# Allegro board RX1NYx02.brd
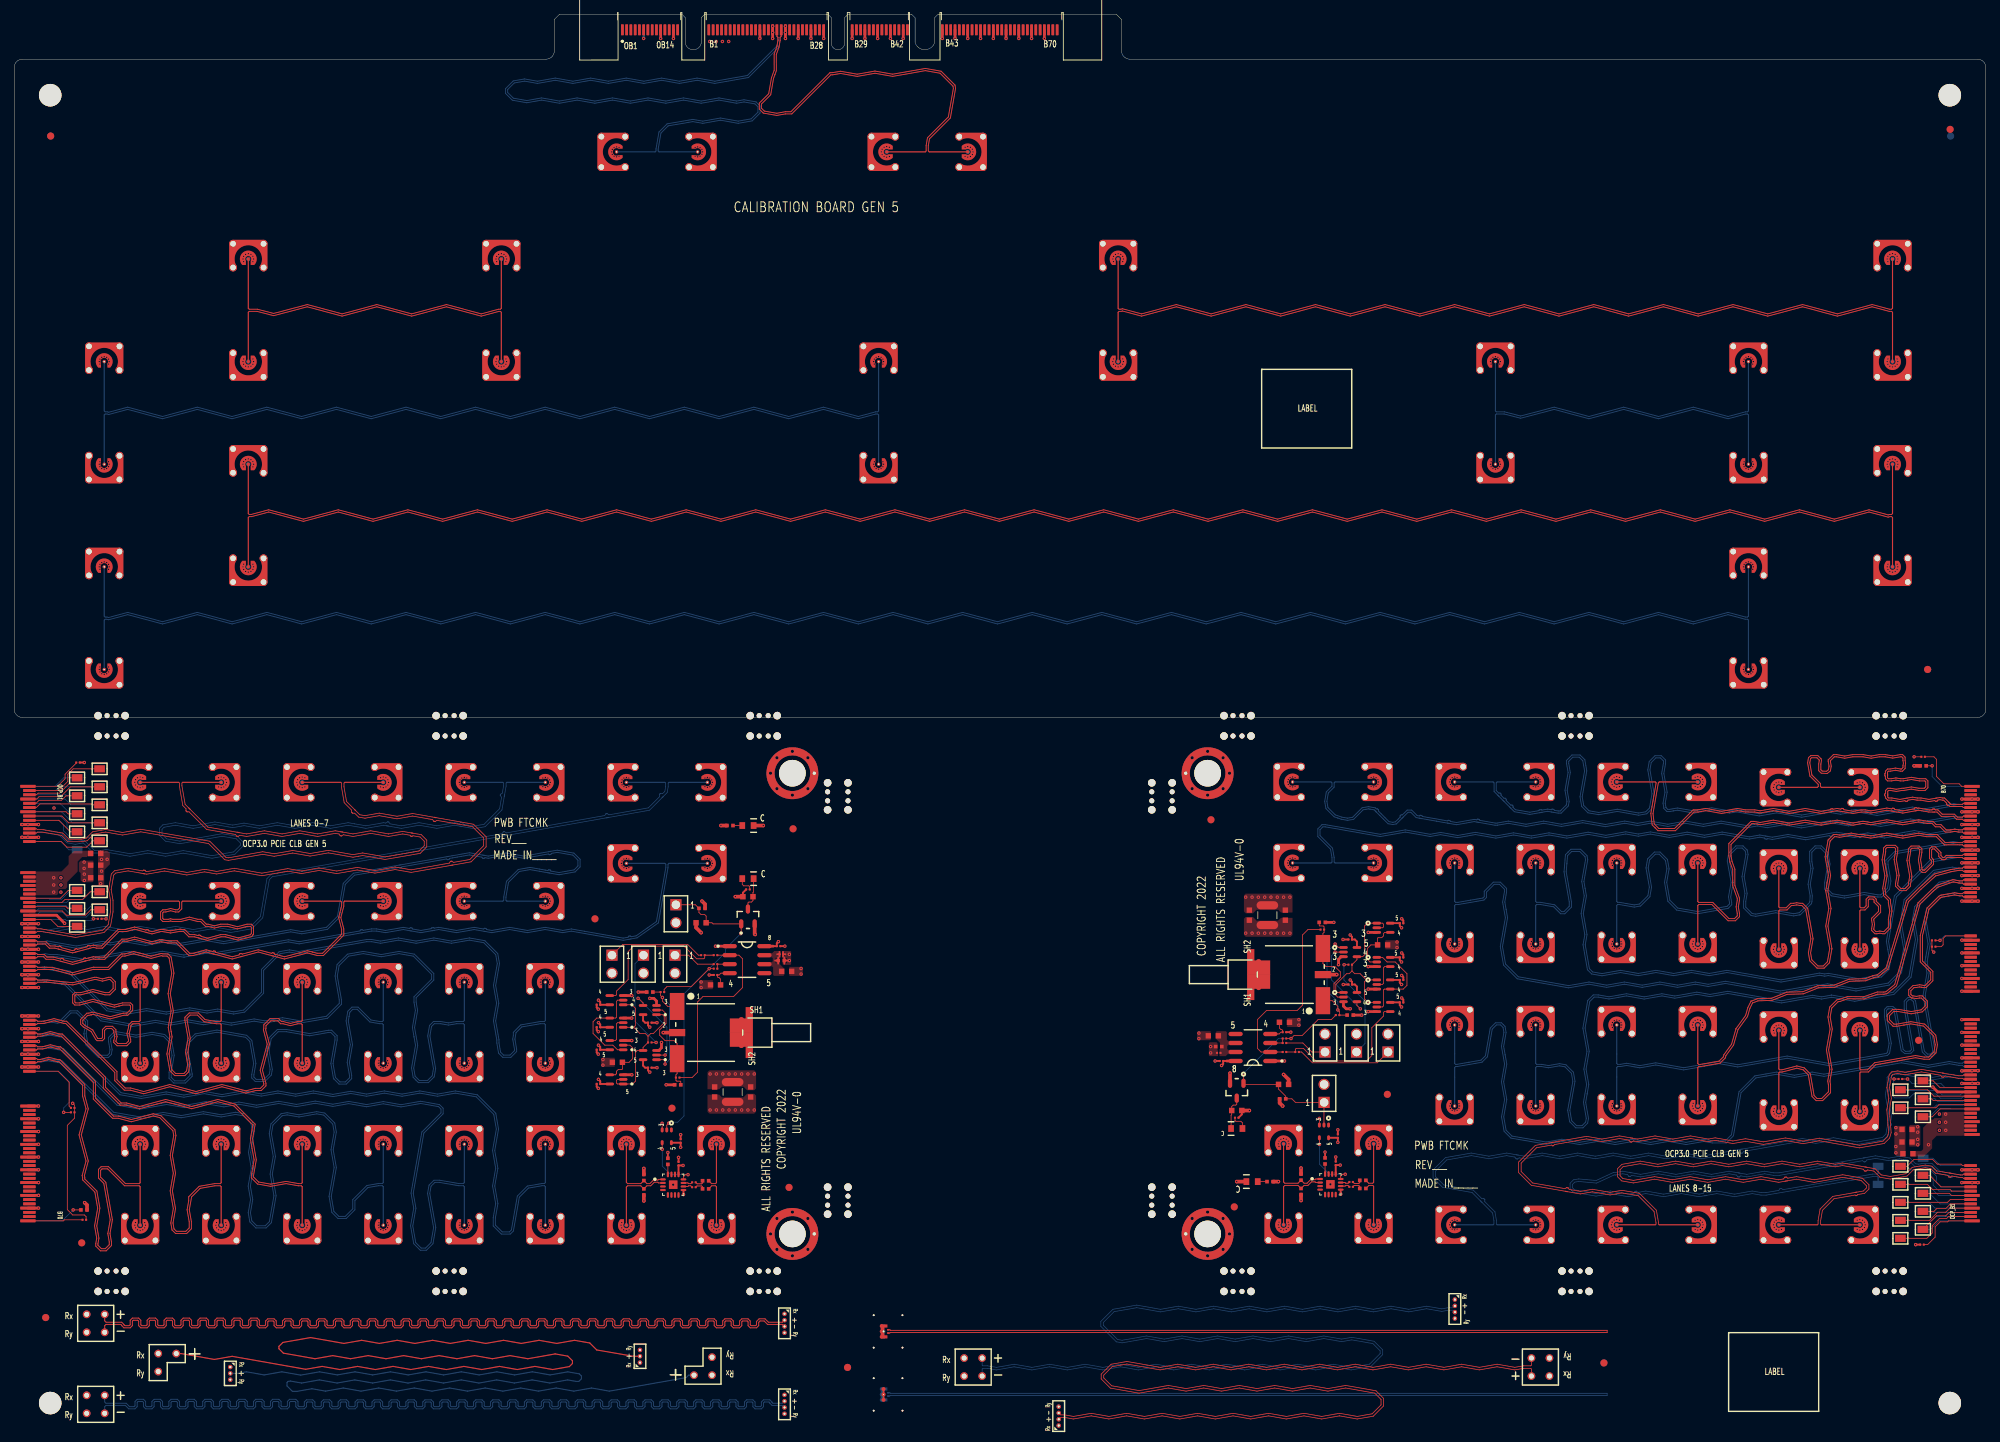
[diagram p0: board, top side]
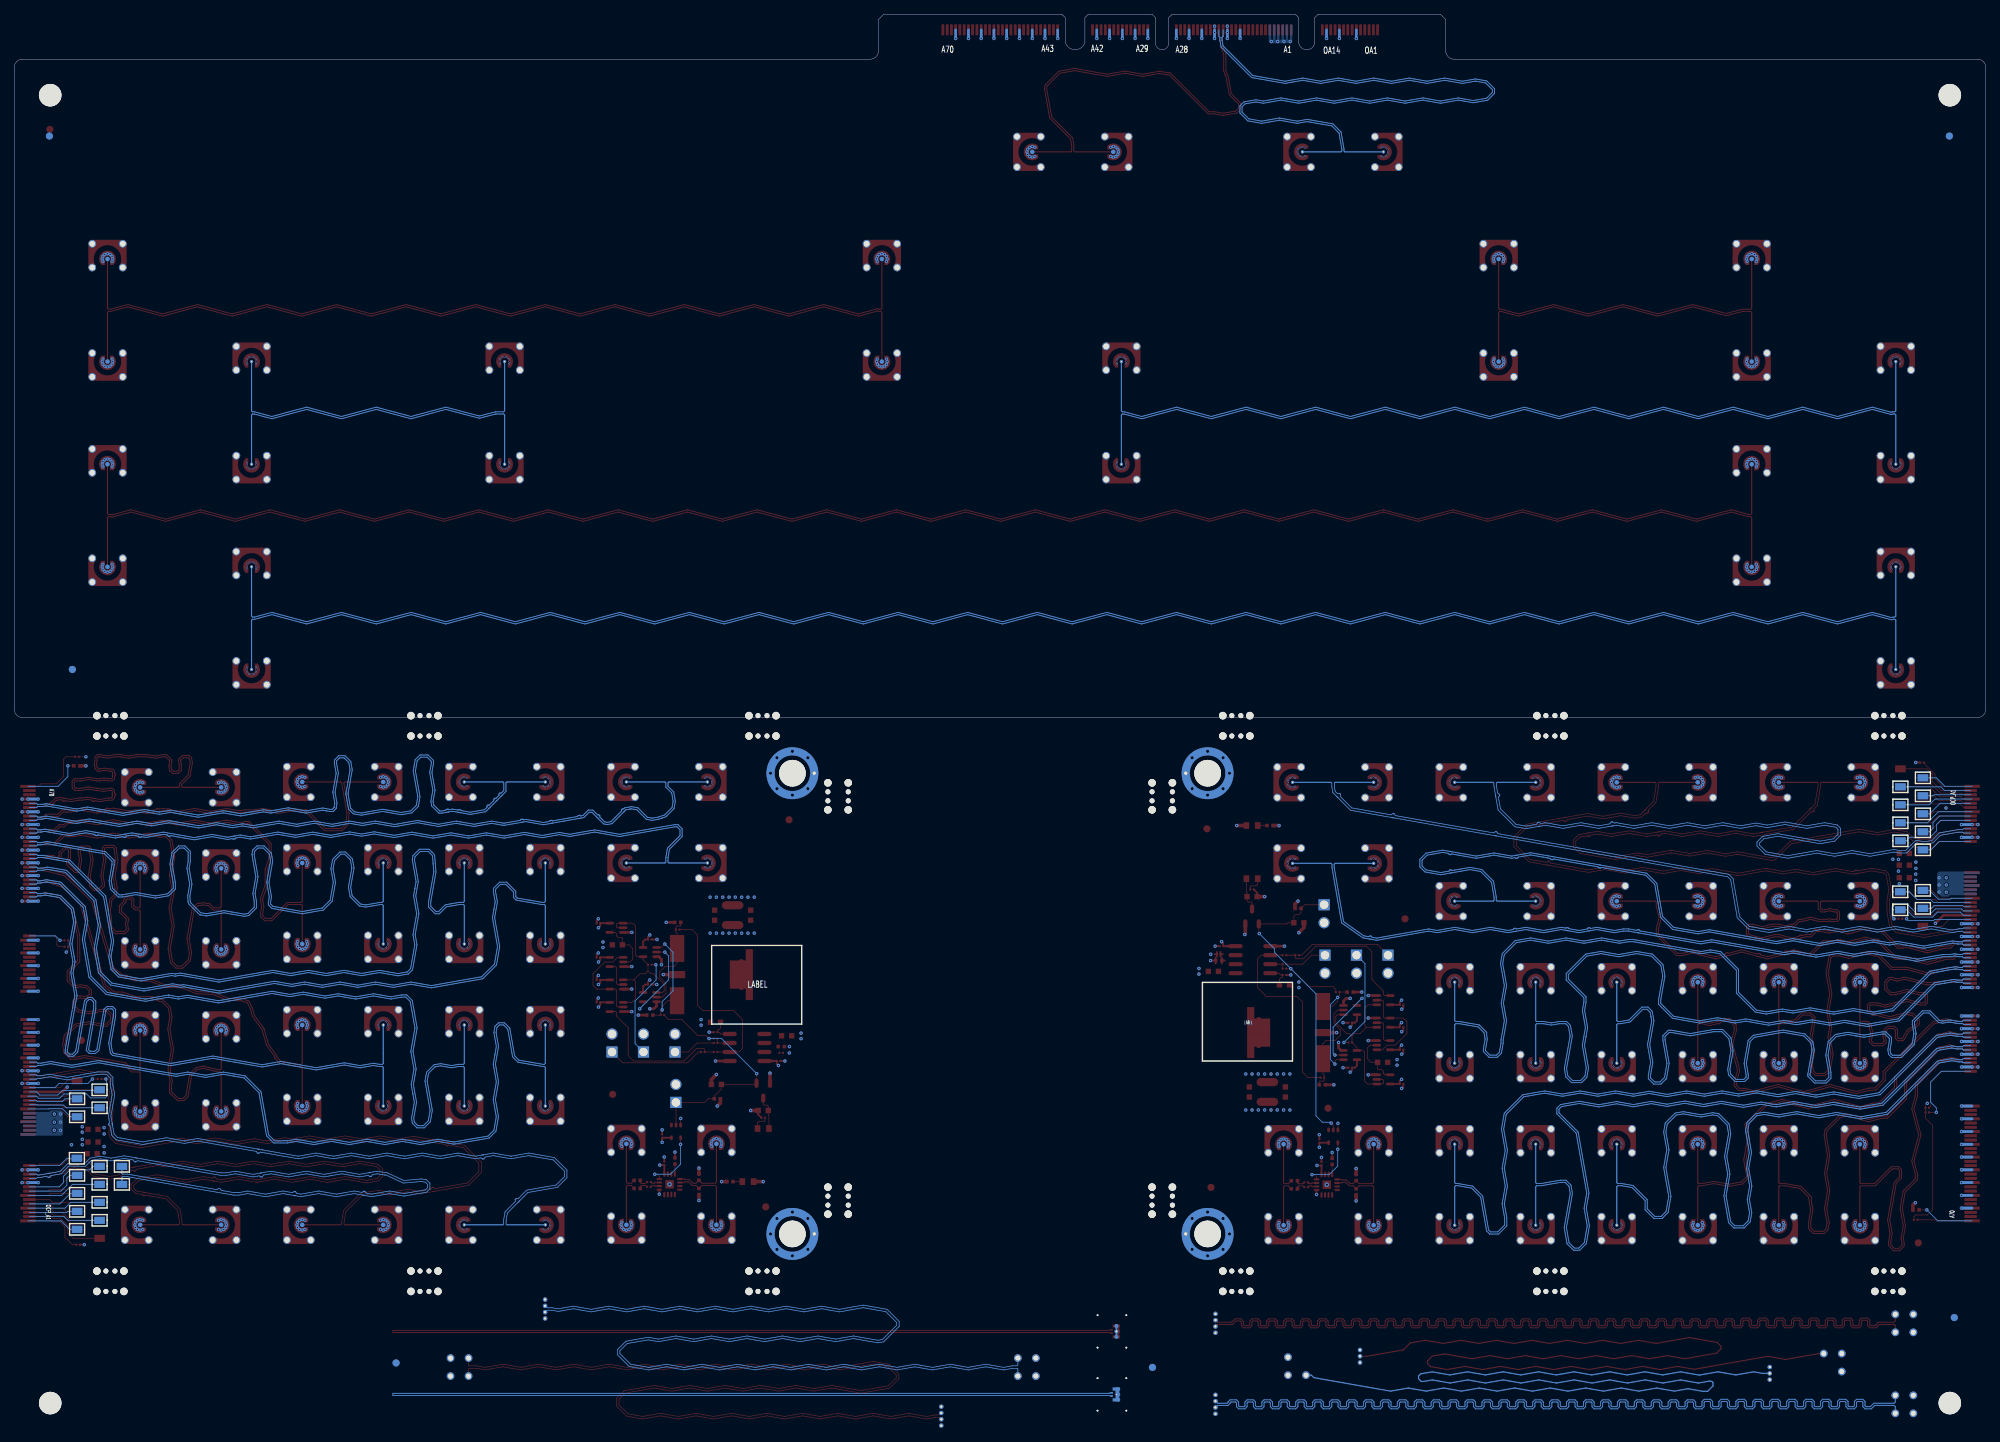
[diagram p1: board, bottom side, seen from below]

Outline 278.08 x 99.23 mm; copper layers: TOP, GND, VCC, GD2, GD3, BOTTOM. Coordinates in mm from the lower left corner of the outline.
Outline path: 0,91.7 arc(0.35,92.54) 1.18,92.88 75,92.88 arc(75.84,93.23) 76.18,94.06 76.18,98.48 76.93,99.23 94.04,99.23 94.16,99.23 94.66,98.73 94.66,95.3 arc(94.97,94.54) 95.72,94.23 95.84,94.23 arc(96.59,94.54) 96.91,95.3 96.91,98.73 97.41,99.23 97.53,99.23 114.51,99.23 114.76,99.23 115.26,98.73 115.26,95.12 arc(115.52,94.49) 116.15,94.23 116.22,94.23 arc(116.85,94.49) 117.11,95.12 117.11,98.48 117.11,98.73 117.61,99.23 117.86,99.23 126.45,99.23 126.57,99.23 127.07,98.73 127.07,95.23 arc(127.57,94.51) 128.41,94.23 128.47,94.23 arc(129.31,94.51) 129.82,95.23 129.82,98.73 130.32,99.23 130.44,99.23 155.43,99.23 156.18,98.48 156.18,94.06 arc(156.53,93.23) 157.36,92.88 276.9,92.88 arc(277.74,92.54) 278.08,91.7 278.08,1.18 arc(277.74,0.35) 276.9,0 1.18,0 arc(0.35,0.35) 0,1.18 0,91.7

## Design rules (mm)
constraint set DEFAULT: min track width 0.102
net group BD1_555_OUT: nets BD1_555_OUT BD1_555_OUT_JP
net group CLK1_TRIG_SIGNAL_C_DN: nets CLK1_TRIG_SIGNAL_C_DN CLK1_TRIG_SIGNAL_R_DN
net group CLK1_TRIG_SIGNAL_C_DP: nets CLK1_TRIG_SIGNAL_C_DP CLK1_TRIG_SIGNAL_R_DP
net group CLK2_TRIG_SIGNAL_C_DN: nets CLK2_TRIG_SIGNAL_C_DN CLK2_TRIG_SIGNAL_R_DN
net group CLK2_TRIG_SIGNAL_C_DP: nets CLK2_TRIG_SIGNAL_C_DP CLK2_TRIG_SIGNAL_R_DP
net group N16712697: nets N16712697 N16712704
net group N16815513: nets N16815513 N16816677
net group SET2DIL: nets SET2DIL_85_BOT SET2DIL_85_TOP
net group V_12V_1: nets N16866749 N16866751
net group V_12V_2: nets N16879387 N16879389
net group 12V: nets V_12V_2
net group _UNCONSTRAINED: nets BD1_AUX_PWR_EN BD1_BIF0_N BD1_BIF1_N BD1_BIF2_N BD1_MAIN_PWR_EN BD1_NCSI_ARBIN BD1_NCSI_ARBOUT BD1_NCSI_CRS_DV BD1_NCSI_RXD0 BD1_NCSI_RXD1 BD1_NCSI_TXD0 BD1_NCSI_TXD1 BD1_NCSI_TXEN BD1_NIC_PWR_GOOD BD1_PWRBRK_N BD1_SCAN_DATA_IN BD1_SCAN_DATA_OUT BD1_SCAN_LD_N BD1_SLOT_ID BD1_SMB_SDA BD1_WAKE_N BD2_AUX_PWR_EN BD2_BIF0_N BD2_BIF1_N BD2_BIF2_N BD2_MAIN_PWR_EN BD2_NCSI_ARBIN BD2_NCSI_ARBOUT BD2_NCSI_CRS_DV BD2_NCSI_RXD0 BD2_NCSI_RXD1 BD2_NCSI_TXD0 BD2_NCSI_TXD1 BD2_NCSI_TXEN BD2_NIC_PWR_GOOD BD2_PWRBRK_N BD2_SCAN_DATA_IN BD2_SCAN_DATA_OUT BD2_SCAN_LD_N BD2_SLOT_ID BD2_SMB_SDA BD2_WAKE_N
net group BD1_555_TRI: nets BD1_555_TRI BD1_BTN_NO N16713764 N16713990
net group BD1_PRSNTA_N: nets BD1_PRSNTA_N BD1_PRSNTB0_N BD1_PRSNTB1_N BD1_PRSNTB2_N BD1_PRSNTB3_N
net group BD2_555_OUT: nets BD2_555_OUT BD2_555_OUT_JP BD2_BTN_NC
net group BD2_555_TRI: nets BD2_555_TRI N16815728 N16815771
net group BD2_PRSNTA_N: nets BD2_PRSNTA_N BD2_PRSNTB0_N BD2_PRSNTB1_N BD2_PRSNTB2_N BD2_PRSNTB3_N
net group BD_REFCLK: nets BD1_REFCLK0_DN BD1_REFCLK0_DP BD1_REFCLK1_DN BD1_REFCLK1_DP BD1_REFCLK2_DN BD1_REFCLK2_DP BD1_REFCLK3_DN BD1_REFCLK3_DP BD2_REFCLK0_DN BD2_REFCLK0_DP BD2_REFCLK1_DN BD2_REFCLK1_DP BD2_REFCLK2_DP BD2_REFCLK3_DN BD2_REFCLK3_DP
net group CLK_DIFF: nets CLK1_HOST_TO_TRIGGER_DN CLK1_HOST_TO_TRIGGER_DP CLK2_HOST_TO_TRIGGER_DN CLK2_HOST_TO_TRIGGER_DP
net group CLK_SE: nets BD1_CLK_NCSI BD1_SCAN_CLK BD1_SMB_CLK BD2_CLK_NCSI BD2_SCAN_CLK BD2_SMB_CLK
net group COUPONS: nets Z_42.5_BOT Z_42.5_TOP Z_85D_BOT_DN Z_85D_BOT_DP Z_85D_TOP_DN Z_85D_TOP_DP Z_100D_BOT_DN Z_100D_BOT_DP Z_100D_TOP_DN Z_100D_TOP_DP
net group PE_SIGNALS: nets BD2_PE_OCP_CPU_0_DN BD2_PE_OCP_CPU_0_DP PE_CAL_BOT_OCP_CPU_0_DN PE_CAL_BOT_OCP_CPU_0_DP PE_CPU_OCP_0_DN PE_CPU_OCP_0_DP PE_CPU_OCP_1_DN PE_CPU_OCP_1_DP PE_CPU_OCP_2_DN PE_CPU_OCP_2_DP PE_CPU_OCP_3_DN PE_CPU_OCP_3_DP PE_CPU_OCP_4_DN PE_CPU_OCP_4_DP PE_CPU_OCP_5_DN PE_CPU_OCP_5_DP PE_CPU_OCP_6_DN PE_CPU_OCP_6_DP PE_CPU_OCP_7_DN PE_CPU_OCP_7_DP PE_CPU_OCP_8_DN PE_CPU_OCP_8_DP PE_CPU_OCP_9_DN PE_CPU_OCP_9_DP PE_CPU_OCP_10_DN PE_CPU_OCP_10_DP PE_CPU_OCP_11_DN PE_CPU_OCP_11_DP PE_CPU_OCP_12_DN PE_CPU_OCP_12_DP PE_CPU_OCP_13_DN PE_CPU_OCP_13_DP PE_CPU_OCP_14_DN PE_CPU_OCP_14_DP PE_CPU_OCP_15_DN PE_CPU_OCP_15_DP PE_OCP_CPU_0_DN PE_OCP_CPU_0_DP PE_OCP_CPU_1_DN PE_OCP_CPU_1_DP PE_OCP_CPU_2_DN PE_OCP_CPU_2_DP PE_OCP_CPU_3_DN PE_OCP_CPU_3_DP PE_OCP_CPU_4_DN PE_OCP_CPU_5_DN PE_OCP_CPU_5_DP PE_OCP_CPU_6_DN PE_OCP_CPU_6_DP PE_OCP_CPU_7_DN PE_OCP_CPU_7_DP PE_OCP_CPU_8_DN PE_OCP_CPU_8_DP PE_OCP_CPU_9_DN PE_OCP_CPU_9_DP PE_OCP_CPU_10_DN PE_OCP_CPU_10_DP PE_OCP_CPU_11_DN PE_OCP_CPU_11_DP PE_OCP_CPU_12_DN PE_OCP_CPU_12_DP PE_OCP_CPU_13_DN PE_OCP_CPU_13_DP PE_OCP_CPU_14_DN PE_OCP_CPU_14_DP PE_OCP_CPU_15_DN PE_OCP_CPU_15_DP
net group RESETS: nets BD1_555_RST_N BD1_PERST0_N BD1_PERST1_N BD1_PERST2_N BD1_PERST3_N BD1_SMB_RST_N BD2_555_RST_N BD2_PERST0_N BD2_PERST1_N BD2_PERST2_N BD2_PERST3_N BD2_SLOT_ID1 BD2_SMB_RST_N
nets with their own width: min track width 0.508; nets V_12V_1

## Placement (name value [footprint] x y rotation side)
BD2_P_OCP_CPU_0_N  COAX,FEMALE  [96_MMPX-50-0-3_L1_CASEA]  203.17 -54.81 90 top
BD2_P_OCP_CPU_0_P  COAX,FEMALE  [96_MMPX-50-0-3_L1_CASEA]  203.17 -43.38 270 top
C1  0.1uF  [C0201]  107.81 -32.26 0 top
C2  0.1uF  [C0201]  89.65 -49.41 180 top
C3  0.1uF  [C0201]  82.41 -43.69 0 top
C4  0.1uF  [C0201]  82.41 -40.52 0 top
C5  0.1uF  [C0201]  82.41 -51.69 0 top
C6  10uF  [C0603]  108.95 -35.82 0 top
C7  10uF  [C0603]  98.92 -37.72 180 top
C8  0.1uF  [C0201]  89.65 -43.06 180 top
C9  0.1uF  [C0201]  82.41 -46.87 0 top
C10  10uF  [C0603]  85.07 -48.64 180 top
C11  0.1uF  [C0201]  95.87 -66.27 180 top
C12  0.1uF  [C0201]  95.87 -65.59 180 top
C13  100uF  [C1210_107H]  101.33 -52.84 90 top
C15  2.2uF  [C0603]  103.87 -52.84 90 top
C16  0.1uF  [C0201]  93.7 -62.95 90 top
C20  2.2uF  [C0603]  11.49 -22.61 180 top
C73  10uF  [C0603]  266.97 -59.89 180 top
C74  2.2uF  [C0603]  266.97 -58.12 0 top
C75  0.1uF  [C0201]  170.27 -48.46 180 top
C76  0.1uF  [C0201]  188.44 -31.32 0 top
C77  0.1uF  [C0201]  195.67 -37.03 180 top
C78  0.1uF  [C0201]  195.67 -40.21 180 top
C79  0.1uF  [C0201]  195.67 -29.03 180 top
C80  10uF  [C0603]  169.13 -44.91 180 top
C81  10uF  [C0603]  179.16 -43 0 top
C82  0.1uF  [C0201]  188.44 -37.67 0 top
C83  0.1uF  [C0201]  195.67 -33.86 180 top
C84  10uF  [C0603]  193.01 -32.08 0 top
C85  0.1uF  [C0201]  186.39 -62.9 90 top
C86  0.1uF  [C0201]  188.56 -66.22 180 top
C87  100uF  [C1210_107H]  176.75 -27.89 270 top
C88  10uF  [C0603]  179.29 -27.89 90 top
C89  2.2uF  [C0603]  174.21 -27.89 270 top
C90  0.1uF  [C0201]  188.56 -65.53 180 top
C145  2.2uF  [C0603]  11.49 -19.18 180 top
C146  10uF  [C0603]  11.49 -20.83 180 top
C147  10uF  [C0603]  98.79 -52.84 90 top
C148  0.056uF  [C0402]  88.81 -64.9 270 top
C149  0.056uF  [C0402]  88.81 -66.93 90 top
C150  10uF  [C0603]  103.49 -25.28 180 top
C155  2.2uF  [C0603]  267.1 -61.54 0 top
C156  0.056uF  [C0402]  181.5 -64.85 270 top
C157  10uF  [C0603]  172.43 -55.45 0 top
C158  0.056uF  [C0402]  181.5 -66.88 90 top
C163  1uF  [C0603]  96.89 -28.96 0 top
C165  1uF  [C0603]  179.04 -51.77 180 top
C166  0.1uF  [C0201]  94 -59.75 90 top
C167  0.1uF  [C0201]  186.69 -59.06 90 top
DS_BD1_PWR  APH1608-TD47  [LEDC1608X65N]  103.49 -15.24 0 top
DS_BD1_TRIG  APH1608-TD47  [LEDC1608X65N]  103.49 -22.74 0 top
DS_BD2_PWR  APH1608-TD47  [LEDC1608X65N]  174.59 -65.48 180 top
DS_BD2_TRIG  APH1608-TD47  [LEDC1608X65N]  172.43 -57.99 180 top
J_S2D_BOT  SET2DIL,COUPON  [TP3_PPROBEB]  122.62 -95.51 0 bottom
J_S2D_TOP  SET2DIL,COUPON  [TP3_PPROBEB]  122.62 -86.62 0 top
LBL1  2d_label500x437  [2D_LABEL500X437]  110.49 -48.47 180 bottom
LBL3  2d_label500x437  [2D_LABEL500X437]  179.71 -43.26 180 bottom
LBL4  2d_label500x437  [2D_LABEL500X437]  241.81 -97.89 0 top
LBL5  2d_label500x437  [2D_LABEL500X437]  175.95 38.02 0 top
MH1  .148 DRILL,.288 PAD TOP/BTM  [MH148_G8_288TB]  109.76 -72.86 0 top
MH2  .148 DRILL,.288 PAD TOP/BTM  [MH148_G8_288TB]  109.76 -7.86 0 top
MH5  .148 DRILL,.288 PAD TOP/BTM  [MH148_G8_288TB]  168.32 -72.86 180 top
MH6  .148 DRILL,.288 PAD TOP/BTM  [MH148_G8_288TB]  168.32 -7.86 180 top
NOREF  -  [unnamed]  168.8 -14.43 180 top
NOREF#2  -  [unnamed#2]  61.41 -80.97 0 top
NOREF#3  -  [unnamed#2]  114.73 -68.17 90 top
NOREF#4  -  [unnamed#2]  13.74 -80.97 0 top
NOREF#5  -  [unnamed#2]  264.51 -2.61 0 top
NOREF#6  -  [unnamed]  109.86 -15.7 0 top
NOREF#7  -  [unnamed#2]  163.32 -68.17 90 top
NOREF#8  -  [#3]  0 -101.17 0 top
NOREF#9  -  [unnamed#2]  117.6 -68.17 90 top
NOREF#10  -  [#3]  5.08 -96.73 0 top
NOREF#11  -  [unnamed#2]  114.73 -11.12 90 top
NOREF#12  -  [unnamed]  269.88 6.78 180 top
NOREF#13  -  [unnamed#2]  160.45 -11.12 90 top
NOREF#14  -  [unnamed#2]  172.54 -80.97 0 top
NOREF#15  -  [unnamed#2]  172.54 -2.61 0 top
NOREF#16  -  [unnamed]  193.68 -53.17 180 top
NOREF#17  -  [unnamed]  172.09 -69.04 180 top
NOREF#18  -  [unnamed#2]  61.41 -2.61 0 top
NOREF#19  -  [#3]  5.08 -96.73 0 top
NOREF#20  -  [unnamed]  117.54 -91.7 180 top
NOREF#21  -  [unnamed]  109.28 -66.3 0 top
NOREF#22  -  [#3]  0.63 -80.72 0 top
NOREF#23  -  [unnamed#2]  117.6 -11.12 90 top
NOREF#24  -  [#3]  76.93 99.23 0 top
NOREF#25  -  [unnamed#2]  13.74 -78.1 0 top
NOREF#26  -  [unnamed#2]  105.71 -2.61 0 top
NOREF#27  -  [unnamed#2]  105.71 -78.1 0 top
NOREF#28  -  [unnamed#2]  264.51 0.26 0 top
NOREF#29  -  [unnamed#2]  13.74 0.26 0 top
NOREF#30  -  [unnamed#2]  172.54 -78.1 0 top
NOREF#31  -  [unnamed]  9.53 -74.12 0 top
NOREF#32  -  [unnamed#2]  61.41 0.26 0 top
NOREF#33  -  [unnamed]  4.45 -84.66 180 top
NOREF#34  -  [unnamed]  92.77 -55.12 0 top
NOREF#35  -  [unnamed]  273 87.8 0 top
NOREF#36  -  [unnamed#2]  264.51 -78.1 0 top
NOREF#37  -  [unnamed]  81.91 -28.4 0 top
NOREF#38  -  [#3]  0.63 -101.81 0 top
NOREF#39  -  [unnamed#2]  220.21 -78.1 0 top
NOREF#40  -  [unnamed]  5.08 87.8 0 top
NOREF#41  -  [unnamed#2]  220.21 0.26 0 top
NOREF#42  -  [unnamed#2]  172.54 0.26 0 top
NOREF#43  -  [unnamed#2]  105.71 -80.97 0 top
NOREF#44  -  [#3]  0.63 -101.81 0 top
NOREF#45  -  [unnamed]  5.14 82.04 180 top
NOREF#46  -  [unnamed#2]  163.32 -11.12 90 top
NOREF#47  -  [unnamed#2]  220.21 -2.61 0 top
NOREF#48  -  [unnamed]  268.6 -45.55 180 top
NOREF#49  -  [unnamed]  224.22 -91.06 180 top
NOREF#50  -  [unnamed#2]  105.71 0.26 0 top
NOREF#51  -  [unnamed]  273 -96.73 0 top
NOREF#52  -  [unnamed#2]  13.74 -2.61 0 top
NOREF#53  -  [unnamed#2]  264.51 -80.97 0 top
NOREF#54  -  [unnamed]  273.05 82.98 180 top
NOREF#55  -  [unnamed#2]  160.45 -68.17 90 top
NOREF#56  -  [#3]  5.08 -96.73 0 top
NOREF#57  -  [#3]  278.08 -100.63 0 top
NOREF#58  -  [unnamed#2]  61.41 -78.1 0 top
NOREF#59  -  [unnamed#2]  220.21 -80.97 0 top
NOREF#60  -  [unnamed]  5.08 -96.73 0 top
NOREF#61  -  [unnamed]  4.45 -84.66 0 bottom
NOREF#62  -  [unnamed]  269.88 6.78 0 bottom
NOREF#63  -  [unnamed]  224.22 -91.06 0 bottom
NOREF#64  -  [unnamed]  5.14 82.04 0 bottom
NOREF#65  -  [unnamed]  117.54 -91.7 0 bottom
NOREF#66  -  [unnamed]  273.11 82.04 0 bottom
P1  2X1,VERT,HDR  [BERG1X2]  84.31 -33.53 0 top
P2  2X1,VERT,HDR  [BERG1X2]  88.76 -33.53 0 top
P3  2X1,VERT,HDR  [BERG1X2]  93.2 -33.53 0 top
P7  2X1,VERT,HDR  [BERG1X2]  193.77 -47.19 180 top
P8  2X1,VERT,HDR  [BERG1X2]  189.32 -47.19 180 top
P9  2X1,VERT,HDR  [BERG1X2]  184.88 -47.19 180 top
P13  2X1,VERT,HDR  [BERG1X2]  93.33 -26.42 0 top
P15  2X1,VERT,HDR  [BERG1X2]  184.75 -54.31 180 top
P_BD1_CLK0_N  COAX,FEMALE  [96_MMPX-50-0-3_L1_CASEA#2]  40.62 -9.15 0 top
P_BD1_CLK0_P  COAX,FEMALE  [96_MMPX-50-0-3_L1_CASEA#2]  52.05 -9.15 180 top
P_BD1_CLK1_N  COAX,FEMALE  [96_MMPX-50-0-3_L1_CASEA]  86.34 -9.15 0 top
P_BD1_CLK1_P  COAX,FEMALE  [96_MMPX-50-0-3_L1_CASEA]  97.77 -9.15 180 top
P_BD1_CLK2_N  COAX,FEMALE  [96_MMPX-50-0-3_L1_CASEA#2]  17.76 -9.15 0 top
P_BD1_CLK2_P  COAX,FEMALE  [96_MMPX-50-0-3_L1_CASEA#2]  29.19 -9.15 180 top
P_BD1_CLK3_N  COAX,FEMALE  [96_MMPX-50-0-3_L1_CASEA]  63.48 -9.15 0 top
P_BD1_CLK3_P  COAX,FEMALE  [96_MMPX-50-0-3_L1_CASEA]  74.91 -9.15 180 top
P_BD1_CMTS_N  COAX,FEMALE  [96_MMPX-50-0-3_L1_CASEA#2]  99.04 -60.2 270 top
P_BD1_CMTS_P  COAX,FEMALE  [96_MMPX-50-0-3_L1_CASEA#2]  99.04 -71.63 90 top
P_BD1_TRIG_IN_N  COAX,FEMALE  [96_MMPX-50-0-3_L1_CASEA#2]  86.34 -71.63 90 top
P_BD1_TRIG_IN_P  COAX,FEMALE  [96_MMPX-50-0-3_L1_CASEA#2]  86.34 -60.2 270 top
P_BD2_CLK0_N  COAX,FEMALE  [96_MMPX-50-0-3_L1_CASEA#2]  237.46 -71.58 180 top
P_BD2_CLK0_P  COAX,FEMALE  [96_MMPX-50-0-3_L1_CASEA#2]  226.03 -71.58 0 top
P_BD2_CLK1_N  COAX,FEMALE  [96_MMPX-50-0-3_L1_CASEA]  214.6 -71.58 180 top
P_BD2_CLK1_P  COAX,FEMALE  [96_MMPX-50-0-3_L1_CASEA]  203.17 -71.58 0 top
P_BD2_CLK2_N  COAX,FEMALE  [96_MMPX-50-0-3_L1_CASEA#2]  260.32 -71.58 180 top
P_BD2_CLK2_P  COAX,FEMALE  [96_MMPX-50-0-3_L1_CASEA#2]  248.89 -71.58 0 top
P_BD2_CMTS_N  COAX,FEMALE  [96_MMPX-50-0-3_L1_CASEA#2]  191.74 -60.15 270 top
P_BD2_CMTS_P  COAX,FEMALE  [96_MMPX-50-0-3_L1_CASEA#2]  191.74 -71.58 90 top
P_BD2_TRIG_IN_N  COAX,FEMALE  [96_MMPX-50-0-3_L1_CASEA#2]  179.04 -71.58 90 top
P_BD2_TRIG_IN_P  COAX,FEMALE  [96_MMPX-50-0-3_L1_CASEA#2]  179.04 -60.15 270 top
P_CAL_CPU_OCP_0_N1  COAX,FEMALE  [96_MMPX-50-0-3_L1_CASEA#2]  123.06 79.8 0 top
P_CAL_CPU_OCP_0_P1  COAX,FEMALE  [96_MMPX-50-0-3_L1_CASEA#2]  134.49 79.8 180 top
P_CAL_OCP_CPU_B_0_N  COAX,FEMALE  [96_MMPX-50-0-3_L1_CASEA]  84.96 79.8 0 top
P_CAL_OCP_CPU_B_0_P  COAX,FEMALE  [96_MMPX-50-0-3_L1_CASEA]  96.39 79.8 180 top
P_CPU_OCP_0_N  COAX,FEMALE  [96_MMPX-50-0-3_L1_CASEA#2]  17.76 -25.91 0 top
P_CPU_OCP_0_P  COAX,FEMALE  [96_MMPX-50-0-3_L1_CASEA#2]  29.19 -25.91 180 top
P_CPU_OCP_1_N  COAX,FEMALE  [96_MMPX-50-0-3_L1_CASEA#2]  40.62 -25.91 0 top
P_CPU_OCP_1_P  COAX,FEMALE  [96_MMPX-50-0-3_L1_CASEA#2]  52.05 -25.91 180 top
P_CPU_OCP_2_N  COAX,FEMALE  [96_MMPX-50-0-3_L1_CASEA#2]  29.19 -37.34 270 top
P_CPU_OCP_2_P  COAX,FEMALE  [96_MMPX-50-0-3_L1_CASEA#2]  29.19 -48.77 90 top
P_CPU_OCP_3_N  COAX,FEMALE  [96_MMPX-50-0-3_L1_CASEA#2]  17.76 -37.34 270 top
P_CPU_OCP_3_P  COAX,FEMALE  [96_MMPX-50-0-3_L1_CASEA#2]  17.76 -48.77 90 top
P_CPU_OCP_4_N  COAX,FEMALE  [96_MMPX-50-0-3_L1_CASEA#2]  40.62 -37.34 270 top
P_CPU_OCP_4_P  COAX,FEMALE  [96_MMPX-50-0-3_L1_CASEA#2]  40.62 -48.77 90 top
P_CPU_OCP_5_N  COAX,FEMALE  [96_MMPX-50-0-3_L1_CASEA#2]  40.62 -60.2 270 top
P_CPU_OCP_5_P  COAX,FEMALE  [96_MMPX-50-0-3_L1_CASEA#2]  40.62 -71.63 90 top
P_CPU_OCP_6_N  COAX,FEMALE  [96_MMPX-50-0-3_L1_CASEA#2]  29.19 -60.2 270 top
P_CPU_OCP_6_P  COAX,FEMALE  [96_MMPX-50-0-3_L1_CASEA#2]  29.19 -71.63 90 top
P_CPU_OCP_7_N  COAX,FEMALE  [96_MMPX-50-0-3_L1_CASEA#2]  17.76 -60.2 270 top
P_CPU_OCP_7_P  COAX,FEMALE  [96_MMPX-50-0-3_L1_CASEA#2]  17.76 -71.63 90 top
P_CPU_OCP_8_N  COAX,FEMALE  [96_MMPX-50-0-3_L1_CASEA#2]  260.32 -55.58 90 top
P_CPU_OCP_8_P  COAX,FEMALE  [96_MMPX-50-0-3_L1_CASEA#2]  260.32 -44.15 270 top
P_CPU_OCP_9_N  COAX,FEMALE  [96_MMPX-50-0-3_L1_CASEA#2]  248.89 -55.58 90 top
P_CPU_OCP_9_P  COAX,FEMALE  [96_MMPX-50-0-3_L1_CASEA#2]  248.89 -44.15 270 top
P_CPU_OCP_10_N  COAX,FEMALE  [96_MMPX-50-0-3_L1_CASEA#2]  237.46 -54.81 90 top
P_CPU_OCP_10_P  COAX,FEMALE  [96_MMPX-50-0-3_L1_CASEA#2]  237.46 -43.38 270 top
P_CPU_OCP_11_N  COAX,FEMALE  [96_MMPX-50-0-3_L1_CASEA#2]  260.32 -32.72 90 top
P_CPU_OCP_11_P  COAX,FEMALE  [96_MMPX-50-0-3_L1_CASEA#2]  260.32 -21.29 270 top
P_CPU_OCP_12_N  COAX,FEMALE  [96_MMPX-50-0-3_L1_CASEA#2]  248.89 -32.72 90 top
P_CPU_OCP_12_P  COAX,FEMALE  [96_MMPX-50-0-3_L1_CASEA#2]  248.89 -21.29 270 top
P_CPU_OCP_13_N  COAX,FEMALE  [96_MMPX-50-0-3_L1_CASEA#2]  237.46 -31.95 90 top
P_CPU_OCP_13_P  COAX,FEMALE  [96_MMPX-50-0-3_L1_CASEA#2]  237.46 -20.52 270 top
P_CPU_OCP_14_N  COAX,FEMALE  [96_MMPX-50-0-3_L1_CASEA#2]  226.03 -9.09 0 top
P_CPU_OCP_14_P  COAX,FEMALE  [96_MMPX-50-0-3_L1_CASEA#2]  237.46 -9.09 180 top
P_CPU_OCP_15_N  COAX,FEMALE  [96_MMPX-50-0-3_L1_CASEA#2]  260.32 -9.86 180 top
P_CPU_OCP_15_P  COAX,FEMALE  [96_MMPX-50-0-3_L1_CASEA#2]  248.89 -9.86 0 top
P_OCP1  CON,EC,168,.6MM,S,G,ST  [CON_AMP_EDGE_ME101681340131X]  5.21 -40.31 90 top
P_OCP2  CON,EC,168,.6MM,S,G,ST  [CON_AMP_EDGE_ME101681340131X]  272.87 -40.42 270 top
P_OCP_CPU_0_N  COAX,FEMALE  [96_MMPX-50-0-3_L1_CASEA]  74.91 -25.91 180 top
P_OCP_CPU_0_P  COAX,FEMALE  [96_MMPX-50-0-3_L1_CASEA]  63.48 -25.91 0 top
P_OCP_CPU_1_N  COAX,FEMALE  [96_MMPX-50-0-3_L1_CASEA]  86.34 -20.58 0 top
P_OCP_CPU_1_P  COAX,FEMALE  [96_MMPX-50-0-3_L1_CASEA]  97.77 -20.58 180 top
P_OCP_CPU_2_N  COAX,FEMALE  [96_MMPX-50-0-3_L1_CASEA]  74.91 -37.34 270 top
P_OCP_CPU_2_P  COAX,FEMALE  [96_MMPX-50-0-3_L1_CASEA]  74.91 -48.77 90 top
P_OCP_CPU_3_N  COAX,FEMALE  [96_MMPX-50-0-3_L1_CASEA]  63.48 -37.34 270 top
P_OCP_CPU_3_P  COAX,FEMALE  [96_MMPX-50-0-3_L1_CASEA]  63.48 -48.77 90 top
P_OCP_CPU_4_N  COAX,FEMALE  [96_MMPX-50-0-3_L1_CASEA]  52.05 -37.34 270 top
P_OCP_CPU_4_P  COAX,FEMALE  [96_MMPX-50-0-3_L1_CASEA]  52.05 -48.77 90 top
P_OCP_CPU_5_N  COAX,FEMALE  [96_MMPX-50-0-3_L1_CASEA]  74.91 -60.2 270 top
P_OCP_CPU_5_P  COAX,FEMALE  [96_MMPX-50-0-3_L1_CASEA]  74.91 -71.63 90 top
P_OCP_CPU_6_N  COAX,FEMALE  [96_MMPX-50-0-3_L1_CASEA]  63.48 -60.2 270 top
P_OCP_CPU_6_P  COAX,FEMALE  [96_MMPX-50-0-3_L1_CASEA]  63.48 -71.63 90 top
P_OCP_CPU_7_N  COAX,FEMALE  [96_MMPX-50-0-3_L1_CASEA]  52.05 -60.2 270 top
P_OCP_CPU_7_P  COAX,FEMALE  [96_MMPX-50-0-3_L1_CASEA]  52.05 -71.63 90 top
P_OCP_CPU_8_N  COAX,FEMALE  [96_MMPX-50-0-3_L1_CASEA]  226.03 -54.81 90 top
P_OCP_CPU_8_P  COAX,FEMALE  [96_MMPX-50-0-3_L1_CASEA]  226.03 -43.38 270 top
P_OCP_CPU_9_N  COAX,FEMALE  [96_MMPX-50-0-3_L1_CASEA]  214.6 -54.81 90 top
P_OCP_CPU_9_P  COAX,FEMALE  [96_MMPX-50-0-3_L1_CASEA]  214.6 -43.38 270 top
P_OCP_CPU_10_N  COAX,FEMALE  [96_MMPX-50-0-3_L1_CASEA]  203.17 -31.95 90 top
P_OCP_CPU_10_P  COAX,FEMALE  [96_MMPX-50-0-3_L1_CASEA]  203.17 -20.52 270 top
P_OCP_CPU_11_N  COAX,FEMALE  [96_MMPX-50-0-3_L1_CASEA]  214.6 -31.95 90 top
P_OCP_CPU_11_P  COAX,FEMALE  [96_MMPX-50-0-3_L1_CASEA]  214.6 -20.52 270 top
P_OCP_CPU_12_N  COAX,FEMALE  [96_MMPX-50-0-3_L1_CASEA]  226.03 -31.95 90 top
P_OCP_CPU_12_P  COAX,FEMALE  [96_MMPX-50-0-3_L1_CASEA]  226.03 -20.52 270 top
P_OCP_CPU_13_N  COAX,FEMALE  [96_MMPX-50-0-3_L1_CASEA]  191.74 -20.52 180 top
P_OCP_CPU_13_P  COAX,FEMALE  [96_MMPX-50-0-3_L1_CASEA]  180.31 -20.52 0 top
P_OCP_CPU_14_N  COAX,FEMALE  [96_MMPX-50-0-3_L1_CASEA]  180.31 -9.09 0 top
P_OCP_CPU_14_P  COAX,FEMALE  [96_MMPX-50-0-3_L1_CASEA]  191.74 -9.09 180 top
P_OCP_CPU_15_N  COAX,FEMALE  [96_MMPX-50-0-3_L1_CASEA]  203.17 -9.09 0 top
P_OCP_CPU_15_P  COAX,FEMALE  [96_MMPX-50-0-3_L1_CASEA]  214.6 -9.09 180 top
P_OCPSTRDL  CONNECTOR 168PIN 60P  [AMP_STRDL_168PIN_60P]  116.44 98.98 180 top
P_SMA_BOT_2IN_DN_1  COAX,FEMALE  [96_MMPX-50-0-3_L1_CASEA]  208.92 35.73 90 top
P_SMA_BOT_2IN_DN_2  COAX,FEMALE  [96_MMPX-50-0-3_L1_CASEA]  244.6 35.73 90 top
P_SMA_BOT_2IN_DP_1  COAX,FEMALE  [96_MMPX-50-0-3_L1_CASEA]  244.6 50.21 270 top
P_SMA_BOT_2IN_DP_2  COAX,FEMALE  [96_MMPX-50-0-3_L1_CASEA]  208.92 50.21 270 top
P_SMA_BOT_5IN_DN_1  COAX,FEMALE  [96_MMPX-50-0-3_L1_CASEA]  12.7 50.21 270 top
P_SMA_BOT_5IN_DN_2  COAX,FEMALE  [96_MMPX-50-0-3_L1_CASEA]  121.92 50.21 270 top
P_SMA_BOT_5IN_DP_1  COAX,FEMALE  [96_MMPX-50-0-3_L1_CASEA]  12.7 35.73 90 top
P_SMA_BOT_5IN_DP_2  COAX,FEMALE  [96_MMPX-50-0-3_L1_CASEA]  121.92 35.73 90 top
P_SMA_BOT_10IN_DN_1  COAX,FEMALE  [96_MMPX-50-0-3_L1_CASEA]  244.6 21.26 270 top
P_SMA_BOT_10IN_DN_2  COAX,FEMALE  [96_MMPX-50-0-3_L1_CASEA]  12.7 21.26 270 top
P_SMA_BOT_10IN_DP_1  COAX,FEMALE  [96_MMPX-50-0-3_L1_CASEA]  244.6 6.78 90 top
P_SMA_BOT_10IN_DP_2  COAX,FEMALE  [96_MMPX-50-0-3_L1_CASEA]  12.7 6.78 90 top
P_SMA_TOP_2IN_DN_1  COAX,FEMALE  [96_MMPX-50-0-3_L1_CASEA#2]  33.02 50.21 90 top
P_SMA_TOP_2IN_DN_2  COAX,FEMALE  [96_MMPX-50-0-3_L1_CASEA#2]  68.71 50.21 90 top
P_SMA_TOP_2IN_DP_1  COAX,FEMALE  [96_MMPX-50-0-3_L1_CASEA#2]  33.02 64.69 270 top
P_SMA_TOP_2IN_DP_2  COAX,FEMALE  [96_MMPX-50-0-3_L1_CASEA#2]  68.71 64.69 270 top
P_SMA_TOP_5IN_DN_1  COAX,FEMALE  [96_MMPX-50-0-3_L1_CASEA#2]  155.7 64.69 270 top
P_SMA_TOP_5IN_DN_2  COAX,FEMALE  [96_MMPX-50-0-3_L1_CASEA#2]  264.92 64.69 270 top
P_SMA_TOP_5IN_DP_1  COAX,FEMALE  [96_MMPX-50-0-3_L1_CASEA#2]  155.7 50.21 90 top
P_SMA_TOP_5IN_DP_2  COAX,FEMALE  [96_MMPX-50-0-3_L1_CASEA#2]  264.92 50.21 90 top
P_SMA_TOP_10IN_DN_1  COAX,FEMALE  [96_MMPX-50-0-3_L1_CASEA#2]  33.02 35.73 270 top
P_SMA_TOP_10IN_DN_2  COAX,FEMALE  [96_MMPX-50-0-3_L1_CASEA#2]  264.92 35.73 270 top
P_SMA_TOP_10IN_DP_1  COAX,FEMALE  [96_MMPX-50-0-3_L1_CASEA#2]  33.02 21.26 90 top
P_SMA_TOP_10IN_DP_2  COAX,FEMALE  [96_MMPX-50-0-3_L1_CASEA#2]  264.92 21.26 90 top
Q1  2N7002K  [SOT95P237X117_3N]  103.49 -28.07 90 top
Q3  2N7002K  [SOT95P237X117_3N]  172.43 -52.65 270 top
R1  0  [R0201]  8.25 -55.07 0 top
R2  0  [R0201]  8.25 -55.71 0 top
R3  0  [R0201]  12.07 -28.4 0 top
R5  4.7K  [R0201]  9 -6.35 0 top
R6  0  [R0201]  9.89 -70.87 0 top
R7  0  [R0201]  91.42 -38.74 0 top
R8  0  [R0201]  93.58 -50.8 0 top
R9  10K  [R0402]  89.65 -38.74 180 top
R10  1K  [R0201]  97.14 -33.53 180 top
R11  10K  [R0402]  108.19 -34.29 0 top
R12  1K  [R0201]  89.65 -45.85 0 top
R13  1K  [R0201]  108.19 -33.4 0 top
R14  0  [R0201]  98.92 -33.53 0 top
R15  1K  [R0201]  98.92 -36.33 180 top
R16  1K  [R0201]  98.92 -34.8 0 top
R17  10K  [R0402]  93.58 -51.82 180 top
R18  0  [R0201]  98.92 -35.44 0 top
R19  24.3  [R0402]  97.52 -66.5 0 top
R20  130  [R0402]  100.95 -15.24 0 top
R21  24.3  [R0402]  97.52 -65.36 0 top
R78  0  [R0201]  270.73 -32.33 180 top
R79  4.7K  [R0201]  269.08 -74.37 180 top
R80  0  [R0201]  270.73 -31.45 180 top
R81  0  [R0201]  266.03 -51 180 top
R82  0  [R0201]  269.24 -5.54 180 top
R84  0  [R0201]  186.66 -41.99 180 top
R85  0  [R0201]  184.5 -29.92 180 top
R86  10K  [R0402]  188.44 -41.99 0 top
R87  1K  [R0201]  180.94 -47.19 0 top
R88  1K  [R0201]  169.89 -47.32 180 top
R89  10K  [R0402]  169.89 -46.43 180 top
R90  1K  [R0201]  188.44 -34.87 180 top
R91  0  [R0201]  179.16 -47.19 180 top
R92  1K  [R0201]  179.16 -44.4 0 top
R93  1K  [R0201]  179.16 -45.92 180 top
R94  10K  [R0402]  184.5 -28.91 0 top
R95  0  [R0201]  179.16 -45.29 180 top
R96  24.3  [R0402]  190.21 -66.45 0 top
R97  130  [R0402]  177.13 -65.48 180 top
R99  24.3  [R0402]  190.21 -65.3 0 top
R154  1K  [R0201]  103.49 -24.26 180 top
R156  1K  [R0201]  172.43 -56.46 0 top
R158  10K  [R0402]  97.01 -26.93 0 top
R160  10K  [R0402]  178.91 -53.8 180 top
R164  100K  [R0402]  9.84 -69.47 0 top
R166  100K  [R0402]  269.24 -6.81 180 top
R167  10K  [R0402]  92.19 -62.62 270 top
R168  10K  [R0402]  184.89 -62.56 270 top
SW1  SPDT PUSHBUTTON  [SW3PSMRA_2SH]  98.03 -44.45 270 top
SW3  SPDT PUSHBUTTON  [SW3PSMRA_2SH]  180.05 -36.27 90 top
TP1  TEST PAD  [TP_REC1P00X1P50]  12.05 -12.32 270 top
TP2  TEST PAD  [TP_REC1P00X1P50]  8.87 -13.59 270 top
TP3  TEST PAD  [TP_REC1P00X1P50]  8.87 -8.51 90 bottom
TP4  TEST PAD  [TP_REC1P00X1P50]  12.05 -9.78 90 bottom
TP5  TEST PAD  [TP_REC1P00X1P50]  8.87 -8.51 270 top
TP6  TEST PAD  [TP_REC1P00X1P50]  8.87 -11.05 90 bottom
TP7  TEST PAD  [TP_REC1P00X1P50]  12.05 -9.78 270 top
TP8  TEST PAD  [TP_REC1P00X1P50]  12.05 -12.32 90 bottom
TP9  TEST PAD  [TP_REC1P00X1P50]  8.87 -13.59 90 bottom
TP10  TEST PAD  [TP_REC1P00X1P50]  8.87 -11.05 270 top
TP11  TEST PAD  [TP_REC1P00X1P50]  12.05 -14.86 90 bottom
TP12  TEST PAD  [TP_REC1P00X1P50]  12.05 -14.86 270 top
TP13  TEST PAD  [TP_REC1P00X1P50]  8.87 -16.13 90 bottom
TP14  TEST PAD  [TP_REC1P00X1P50]  8.87 -16.13 270 top
TP15  TEST PAD  [TP_REC1P00X1P50]  12.05 -17.4 90 bottom
TP16  TEST PAD  [TP_REC1P00X1P50]  12.05 -17.4 270 top
TP17  TEST PAD  [TP_REC1P00X1P50]  8.87 -18.67 90 bottom
TP18  TEST PAD  [TP_REC1P00X1P50]  8.87 -24.39 270 top
TP19  TEST PAD  [TP_REC1P00X1P50]  8.87 -24.39 90 bottom
TP20  TEST PAD  [TP_REC1P00X1P50]  12.07 -24.59 270 top
TP21  TEST PAD  [TP_REC1P00X1P50]  12.07 -24.59 90 bottom
TP22  TEST PAD  [TP_REC1P00X1P50]  8.87 -26.93 270 top
TP23  TEST PAD  [TP_REC1P00X1P50]  8.87 -26.93 90 bottom
TP24  TEST PAD  [TP_REC1P00X1P50]  12.07 -27.13 270 top
TP25  TEST PAD  [TP_REC1P00X1P50]  12.07 -27.13 90 bottom
TP26  TEST PAD  [TP_REC1P00X1P50]  8.87 -29.47 270 top
TP27  TEST PAD  [TP_REC1P00X1P50]  12.05 -7.24 270 top
TP55  TEST PAD  [TP_REC1P00X1P50]  269.21 -72.21 270 bottom
TP56  TEST PAD  [TP_REC1P00X1P50]  266.03 -73.48 90 top
TP57  TEST PAD  [TP_REC1P00X1P50]  266.03 -70.94 270 bottom
TP58  TEST PAD  [TP_REC1P00X1P50]  269.21 -72.21 90 top
TP59  TEST PAD  [TP_REC1P00X1P50]  269.21 -69.67 270 bottom
TP60  TEST PAD  [TP_REC1P00X1P50]  266.03 -70.94 90 top
TP61  TEST PAD  [TP_REC1P00X1P50]  269.21 -69.67 90 top
TP62  TEST PAD  [TP_REC1P00X1P50]  269.21 -67.13 270 bottom
TP63  TEST PAD  [TP_REC1P00X1P50]  266.03 -68.4 90 top
TP64  TEST PAD  [TP_REC1P00X1P50]  269.21 -67.13 90 top
TP65  TEST PAD  [TP_REC1P00X1P50]  266.03 -65.86 270 bottom
TP66  TEST PAD  [TP_REC1P00X1P50]  266.03 -65.86 90 top
TP67  TEST PAD  [TP_REC1P00X1P50]  269.21 -64.59 270 bottom
TP68  TEST PAD  [TP_REC1P00X1P50]  269.21 -64.59 90 top
TP69  TEST PAD  [TP_REC1P00X1P50]  266.03 -63.32 270 bottom
TP70  TEST PAD  [TP_REC1P00X1P50]  266.03 -63.32 90 top
TP71  TEST PAD  [TP_REC1P00X1P50]  269.24 -62.19 270 bottom
TP72  TEST PAD  [TP_REC1P00X1P50]  269.21 -56.34 90 top
TP73  TEST PAD  [TP_REC1P00X1P50]  266.03 -55.07 90 top
TP74  TEST PAD  [TP_REC1P00X1P50]  266.03 -68.4 270 bottom
TP75  TEST PAD  [TP_REC1P00X1P50]  269.21 -56.34 270 bottom
TP76  TEST PAD  [TP_REC1P00X1P50]  266.03 -55.07 270 bottom
TP77  TEST PAD  [TP_REC1P00X1P50]  269.21 -53.8 90 top
TP78  TEST PAD  [TP_REC1P00X1P50]  269.21 -53.8 270 bottom
TP79  TEST PAD  [TP_REC1P00X1P50]  266.03 -52.53 90 top
TP80  TEST PAD  [TP_REC1P00X1P50]  266.03 -52.53 270 bottom
TP81  TEST PAD  [TP_REC1P00X1P50]  269.21 -51.26 90 top
TP82  TEST PAD  [TP_REC1P00X1P50]  262.89 -63.33 270 bottom
TP83  TEST PAD  [TP_REC1P00X1P50]  262.89 -65.87 270 bottom
U1  NC7SZ00  [SOT65P210X110_5N]  89.65 -47.63 180 top
U2  NC7SZ00  [SOT65P210X110_5N]  84.95 -43.06 180 top
U3  NC7SZ00  [SOT65P210X110_5N]  84.95 -39.88 180 top
U4  LMC555  [SOIC127P600X175_8N]  103.36 -34.17 0 top
U5  NC7SZ00  [SOT65P210X110_5N]  84.95 -51.06 180 top
U6  NC7SZ00  [SOT65P210X110_5N]  89.65 -41.28 180 top
U7  NC7SZ00  [SOT65P210X110_5N]  84.95 -46.23 180 top
U17  NC7SZ00  [SOT65P210X110_5N]  188.44 -33.1 0 top
U18  NC7SZ00  [SOT65P210X110_5N]  193.13 -40.84 0 top
U19  NC7SZ00  [SOT65P210X110_5N]  193.13 -37.67 0 top
U20  LMC555  [SOIC127P600X175_8N]  174.72 -46.56 180 top
U21  NC7SZ00  [SOT65P210X110_5N]  193.13 -29.67 0 top
U22  NC7SZ00  [SOT65P210X110_5N]  188.44 -39.45 0 top
U23  NC7SZ00  [SOT65P210X110_5N]  193.13 -34.49 0 top
U24  SY75603ATWL  [QFN50P300X300X90-17]  92.95 -65.92 0 top
U25  SY75603ATWL  [QFN50P300X300X90-17]  185.64 -65.86 0 top
U26  NC7SZ14  [SOT65P210X110_5L]  92.04 -59.09 270 top
U27  NC7SZ14  [SOT65P210X110_5L]  184.73 -58.4 270 top
Z_42.5_BOT  ZSE3PINS2R,IMP COUPON  [ZSE3PINS2R]  98.42 -92.79 180 top
Z_42.5_BOT_END  IMP TP SINGLE ENDED  [IMP_TP_1X3_35P]  30.48 -91.65 270 top
Z_42.5_TOP  ZSE3PINS2R,IMP COUPON  [ZSE3PINS2R]  20.32 -89.74 0 top
Z_42.5_TOP_END  IMP TP SINGLE ENDED  [IMP_TP_1X3_35P]  88.27 -91.01 90 top
Z_85D_BOT  zdi4pins2r  [ZDI4PINS2R]  10.22 -95.63 0 top
Z_85D_BOT_END  imp_tp_diff  [IMP_TP_1X4_35P]  108.65 -95.57 270 top
Z_85D_TOP  zdi4pins2r  [ZDI4PINS2R]  10.22 -84.2 0 top
Z_85D_TOP_END  imp_tp_diff  [IMP_TP_1X4_35P]  108.65 -84.14 270 top
Z_100D_BOT  zdi4pins2r  [ZDI4PINS2R]  133.99 -90.38 0 top
Z_100D_BOT_END  imp_tp_diff  [IMP_TP_1X4_35P]  203.2 -82.12 270 top
Z_100D_TOP  zdi4pins2r  [ZDI4PINS2R]  216.54 -92.92 180 top
Z_100D_TOP_END  imp_tp_diff  [IMP_TP_1X4_35P]  147.32 -99.9 90 top

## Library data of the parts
BD2_P_OCP_CPU_0_N BD2_P_OCP_CPU_0_P P_BD1_CLK1_N P_BD1_CLK1_P P_BD1_CLK3_N P_BD1_CLK3_P P_BD1_TRIG_IN_N P_BD1_TRIG_IN_P P_BD2_CLK1_N P_BD2_CLK1_P P_BD2_TRIG_IN_N P_BD2_TRIG_IN_P P_OCP_CPU_0_N P_OCP_CPU_0_P P_OCP_CPU_1_N P_OCP_CPU_1_P P_OCP_CPU_2_N P_OCP_CPU_2_P P_OCP_CPU_3_N P_OCP_CPU_3_P P_OCP_CPU_4_N P_OCP_CPU_4_P P_OCP_CPU_5_N P_OCP_CPU_5_P P_OCP_CPU_6_N P_OCP_CPU_6_P P_OCP_CPU_7_N P_OCP_CPU_7_P P_OCP_CPU_8_N P_OCP_CPU_8_P P_OCP_CPU_9_N P_OCP_CPU_9_P P_OCP_CPU_10_N P_OCP_CPU_10_P P_OCP_CPU_11_N P_OCP_CPU_11_P P_OCP_CPU_12_N P_OCP_CPU_12_P P_OCP_CPU_13_N P_OCP_CPU_13_P P_OCP_CPU_14_N P_OCP_CPU_14_P P_OCP_CPU_15_N P_OCP_CPU_15_P = g_jack_1: alternate symbols: ((96_mmpx-50-0-3_l6_casea)); room: BRD1
C1-C5 C8 C9 C11 C12 C16 = cap: Tolerance: 10%; User Part Number: MNN3J; alternate symbols: ((CAPC0603X33N,C0201M_FOX,C0201_R4)); tolerance: 10%; signal model: DEFAULT_CAPACITOR_100000pF_2_1; room: BRD1
C6 C7 C10 C146 C147 C150 = cap: User Part Number: 3MRV8; Tolerance: 20%; tolerance: 20%; signal model: DEFAULT_CAPACITOR_1e+07pF_2_1; room: BRD1
C13 = cap: User Part Number: DN761; Tolerance: 20%; tolerance: 20%; signal model: DEFAULT_CAPACITOR_1e+08pF_2_1; room: BRD1
C15 C20 C145 = cap: User Part Number: J6201; Tolerance: 10%; tolerance: 10%; signal model: DEFAULT_CAPACITOR_2.2e+06pF_2_1; room: BRD1
C73 C80 C81 C84 C88 C157 = cap: User Part Number: 3MRV8; Tolerance: 20%; tolerance: 20%; signal model: DEFAULT_CAPACITOR_1e+07pF_2_1; room: BRD2
C74 C89 C155 = cap: User Part Number: J6201; Tolerance: 10%; tolerance: 10%; signal model: DEFAULT_CAPACITOR_2.2e+06pF_2_1; room: BRD2
C75-C79 C82 C83 C85 C86 C90 = cap: Tolerance: 10%; User Part Number: MNN3J; alternate symbols: ((CAPC0603X33N,C0201M_FOX,C0201_R4)); tolerance: 10%; signal model: DEFAULT_CAPACITOR_100000pF_2_1; room: BRD2
C87 = cap: User Part Number: DN761; Tolerance: 20%; tolerance: 20%; signal model: DEFAULT_CAPACITOR_1e+08pF_2_1; room: BRD2
C148 C149 = cap: User Part Number: KN9YT; Tolerance: 10%; tolerance: 10%; signal model: DEFAULT_CAPACITOR_56000pF_2_1; room: BRD1
C156 C158 = cap: User Part Number: KN9YT; Tolerance: 10%; tolerance: 10%; signal model: DEFAULT_CAPACITOR_56000pF_2_1; room: BRD2
C163 = cap: User Part Number: RY497; Tolerance: 10%; tolerance: 10%; signal model: DEFAULT_CAPACITOR_1e+06pF_2_1; room: BRD1
C165 = cap: User Part Number: RY497; Tolerance: 10%; tolerance: 10%; signal model: DEFAULT_CAPACITOR_1e+06pF_2_1; room: BRD2
C166 C167 = cap: Tolerance: 10%; User Part Number: MNN3J; alternate symbols: ((CAPC0603X33N,C0201M_FOX,C0201_R4)); tolerance: 10%; room: BRD2
DS_BD1_PWR DS_BD1_TRIG = g_led_a1_c2: Tolerance: TOL; User Part Number: UJ387; room: BRD1
DS_BD2_PWR DS_BD2_TRIG = g_led_a1_c2: Tolerance: TOL; User Part Number: UJ387; room: BRD2
J_S2D_BOT J_S2D_TOP = tp3_pprobeb_sm-empty: User Part Number: 110408130004
LBL1 = 2d_label500x437: User Part Number: HP126; room: BRD1
LBL3-LBL5 = 2d_label500x437: User Part Number: HP126; room: BRD2
MH1 MH2 = g_1x1_mh: User Part Number: 090730100124; room: BRD1
MH5 MH6 = g_1x1_mh: User Part Number: 090730100124; room: BRD2
P1-P3 P13 = g_2x1: User Part Number: RD013; room: BRD1
P7-P9 P15 = g_2x1: User Part Number: RD013; room: BRD2
P_BD1_CLK0_N P_BD1_CLK0_P P_BD1_CLK2_N P_BD1_CLK2_P P_BD1_CMTS_N P_BD1_CMTS_P P_BD2_CLK0_N P_BD2_CLK0_P P_BD2_CLK2_N P_BD2_CLK2_P P_BD2_CMTS_N P_BD2_CMTS_P P_CAL_CPU_OCP_0_N1 P_CAL_CPU_OCP_0_P1 P_CAL_OCP_CPU_B_0_N P_CAL_OCP_CPU_B_0_P P_CPU_OCP_0_N P_CPU_OCP_0_P P_CPU_OCP_1_N P_CPU_OCP_1_P P_CPU_OCP_2_N P_CPU_OCP_2_P P_CPU_OCP_3_N P_CPU_OCP_3_P P_CPU_OCP_4_N P_CPU_OCP_4_P P_CPU_OCP_5_N P_CPU_OCP_5_P P_CPU_OCP_6_N P_CPU_OCP_6_P P_CPU_OCP_7_N P_CPU_OCP_7_P P_CPU_OCP_8_N P_CPU_OCP_8_P P_CPU_OCP_9_N P_CPU_OCP_9_P P_CPU_OCP_10_N P_CPU_OCP_10_P P_CPU_OCP_11_N P_CPU_OCP_11_P P_CPU_OCP_12_N P_CPU_OCP_12_P P_CPU_OCP_13_N P_CPU_OCP_13_P P_CPU_OCP_14_N P_CPU_OCP_14_P P_CPU_OCP_15_N P_CPU_OCP_15_P P_SMA_BOT_2IN_DN_1 P_SMA_BOT_2IN_DN_2 P_SMA_BOT_2IN_DP_1 P_SMA_BOT_2IN_DP_2 P_SMA_BOT_5IN_DN_1 P_SMA_BOT_5IN_DN_2 P_SMA_BOT_5IN_DP_1 P_SMA_BOT_5IN_DP_2 P_SMA_BOT_10IN_DN_1 P_SMA_BOT_10IN_DN_2 P_SMA_BOT_10IN_DP_1 P_SMA_BOT_10IN_DP_2 P_SMA_TOP_2IN_DN_1 P_SMA_TOP_2IN_DN_2 P_SMA_TOP_2IN_DP_1 P_SMA_TOP_2IN_DP_2 P_SMA_TOP_5IN_DN_1 P_SMA_TOP_5IN_DN_2 P_SMA_TOP_5IN_DP_1 P_SMA_TOP_5IN_DP_2 P_SMA_TOP_10IN_DN_1 P_SMA_TOP_10IN_DN_2 P_SMA_TOP_10IN_DP_1 P_SMA_TOP_10IN_DP_2 = g_jack_0: alternate symbols: ((96_mmpx-50-0-3_l6_casea))
P_OCP1 = c84edg_amp: User Part Number: 7HYMF|EDG; alternate symbols: ((CON_AMP_EDGE_ME101681340131X_alt)); room: BRD1
P_OCP2 = c84edg_amp: User Part Number: 7HYMF|EDG; alternate symbols: ((CON_AMP_EDGE_ME101681340131X_alt)); room: BRD2
P_OCPSTRDL = c84edg_amp
Q1 = ft2n7002k_sot23: User Part Number: FR033; Tolerance: TOL; room: BRD1
Q3 = ft2n7002k_sot23: User Part Number: FR033; Tolerance: TOL; room: BRD2
R1-R3 R6-R8 R14 R18 = res: Tolerance: 5%; User Part Number: YY941; alternate symbols: ((R0201_R4,R0201M_FOX)); tolerance: 5%; signal model: DEFAULT_RESISTOR_0.001OHM_2_1; room: BRD1
R5 = res: Tolerance: 1%; User Part Number: X44H2; alternate symbols: ((R0201_R4,R0201M_FOX)); tolerance: 1%; signal model: DEFAULT_RESISTOR_4700OHM_2_1; room: BRD1
R9 R11 R17 R158 = res: User Part Number: N1256; Tolerance: 1%; tolerance: 1%; signal model: DEFAULT_RESISTOR_10000OHM_2_1; room: BRD1
R10 R12 R13 R15 R16 R154 = res: Tolerance: 1%; User Part Number: 3WWMJ; alternate symbols: ((R0201_R4,R0201M_FOX)); tolerance: 1%; signal model: DEFAULT_RESISTOR_1000.000000OHM_2_1; room: BRD1
R19 R21 = res: User Part Number: H8992; Tolerance: 1%; tolerance: 1%; signal model: DEFAULT_RESISTOR_24.300000OHM_2_1; room: BRD1
R20 = res: User Part Number: J8387; Tolerance: 1%; tolerance: 1%; signal model: DEFAULT_RESISTOR_130.000000OHM_2_1; room: BRD1
R78 R80-R82 R84 R85 R91 R95 = res: Tolerance: 5%; User Part Number: YY941; alternate symbols: ((R0201_R4,R0201M_FOX)); tolerance: 5%; signal model: DEFAULT_RESISTOR_0.001OHM_2_1; room: BRD2
R79 = res: Tolerance: 1%; User Part Number: X44H2; alternate symbols: ((R0201_R4,R0201M_FOX)); tolerance: 1%; signal model: DEFAULT_RESISTOR_4700OHM_2_1; room: BRD2
R86 R89 R94 R160 = res: User Part Number: N1256; Tolerance: 1%; tolerance: 1%; signal model: DEFAULT_RESISTOR_10000OHM_2_1; room: BRD2
R87 R88 R90 R92 R93 R156 = res: Tolerance: 1%; User Part Number: 3WWMJ; alternate symbols: ((R0201_R4,R0201M_FOX)); tolerance: 1%; signal model: DEFAULT_RESISTOR_1000.000000OHM_2_1; room: BRD2
R96 R99 = res: User Part Number: H8992; Tolerance: 1%; tolerance: 1%; signal model: DEFAULT_RESISTOR_24.300000OHM_2_1; room: BRD2
R97 = res: User Part Number: J8387; Tolerance: 1%; tolerance: 1%; signal model: DEFAULT_RESISTOR_130.000000OHM_2_1; room: BRD2
R164 = res: User Part Number: 92259; Tolerance: 5%; tolerance: 5%; signal model: DEFAULT_RESISTOR_100000OHM_2_1; room: BRD1
R166 = res: User Part Number: 92259; Tolerance: 5%; tolerance: 5%; signal model: DEFAULT_RESISTOR_100000OHM_2_1; room: BRD2
R167 R168 = res: User Part Number: N1256; Tolerance: 1%; tolerance: 1%; room: BRD1
SW1 = sw3psmra_spdt: User Part Number: GC8VG; Tolerance: TOL; room: BRD1
SW3 = sw3psmra_spdt: User Part Number: GC8VG; Tolerance: TOL; room: BRD2
TP1-TP27 = g_tp: room: BRD1
TP55-TP83 = g_tp: room: BRD2
U1-U3 U5-U7 = g_nand_1slot_a1_b2: Tolerance: TOL; User Part Number: RPWR7; room: BRD1
U4 = lmc555: Tolerance: TOL; User Part Number: 83011; room: BRD1
U17-U19 U21-U23 = g_nand_1slot_a1_b2: Tolerance: TOL; User Part Number: RPWR7; room: BRD2
U20 = lmc555: Tolerance: TOL; User Part Number: 83011; room: BRD2
U24 U25 = SY75603ATWL
U26 U27 = g_inv_1slot_nc1_a2: Tolerance: TOL; User Part Number: DT962
Z_42.5_BOT Z_42.5_TOP = zse3pins2r: User Part Number: 090730100157; Tolerance: TOL
Z_42.5_BOT_END Z_42.5_TOP_END = imp_tp_se: User Part Number: 090730100116
Z_85D_BOT Z_85D_TOP Z_100D_BOT Z_100D_TOP = zdi4pins2r: User Part Number: 00000; Tolerance: TOL
Z_85D_BOT_END Z_85D_TOP_END Z_100D_BOT_END Z_100D_TOP_END = imp_tp_diff: User Part Number: 00000

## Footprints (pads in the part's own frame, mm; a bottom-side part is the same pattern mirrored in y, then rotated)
2D_LABEL500X437
  round 0 smd: 1(0,0)
96_MMPX-50-0-3_L1_CASEA
  round 0.457 hole 0.203: 1(0,0)
  round 1.092 hole 0.813: 2(1.2,-2.15) 3(-2.15,-2.15) 4(-2.15,2.15) 5(1.2,2.15)
  rect 0.051x0.051 smd: 6(-0.356,0.94)
96_MMPX-50-0-3_L1_CASEA#2
  round 0.457 smd: 1(0,0)
  round 1.092 hole 0.813: 2(1.2,-2.15) 3(-2.15,-2.15) 4(-2.15,2.15) 5(1.2,2.15)
  rect 0.051x0.051 smd: 6(-0.457,1.041)
AMP_STRDL_168PIN_60P
  round 0 hole 2.4 unplated: (-34.24,2.982) (33.98,2.982)
  rect 0.35x1.5 smd: A1(18.465,1.962) A2(17.865,1.962) A3(17.265,1.962) A4(16.665,1.962) A5(16.065,1.962) A6(15.465,1.962) A7(14.865,1.962) A8(14.265,1.962) A9(13.665,1.962) A10(13.065,1.962) A11(12.465,1.962) A12(11.865,1.962) A13(11.265,1.962) A14(10.665,1.962) A15(10.065,1.962) A16(9.465,1.962) A17(8.865,1.962) A18(8.265,1.962) A19(7.665,1.962) A20(7.065,1.962) A21(6.465,1.962) A22(5.865,1.962) A23(5.265,1.962) A24(4.665,1.962) A25(4.065,1.962) A26(3.465,1.962) A27(2.865,1.962) A28(2.265,1.962) A29(-1.745,1.962) A30(-2.345,1.962) A31(-2.945,1.962) A32(-3.545,1.962) A33(-4.145,1.962) A34(-4.745,1.962) A35(-5.345,1.962) A36(-5.945,1.962) A37(-6.545,1.962) A38(-7.145,1.962) A39(-7.745,1.962) A40(-8.345,1.962) A41(-8.945,1.962) A42(-9.545,1.962) A43(-14.455,1.962) A44(-15.055,1.962) A45(-15.655,1.962) A46(-16.255,1.962) A47(-16.855,1.962) A48(-17.455,1.962) A49(-18.055,1.962) A50(-18.655,1.962) A51(-19.255,1.962) A52(-19.855,1.962) A53(-20.455,1.962) A54(-21.055,1.962) A55(-21.655,1.962) A56(-22.255,1.962) A57(-22.855,1.962) A58(-23.455,1.962) A59(-24.055,1.962) A60(-24.655,1.962) A61(-25.255,1.962) A62(-25.855,1.962) A63(-26.455,1.962) A64(-27.055,1.962) A65(-27.655,1.962) A66(-28.255,1.962) A67(-28.855,1.962) A68(-29.455,1.962) A69(-30.055,1.962) A70(-30.655,1.962) B1(18.465,1.962) B2(17.865,1.962) B3(17.265,1.962) B4(16.665,1.962) B5(16.065,1.962) B6(15.465,1.962) B7(14.865,1.962) B8(14.265,1.962) B9(13.665,1.962) B10(13.065,1.962) B11(12.465,1.962) B12(11.865,1.962) B13(11.265,1.962) B14(10.665,1.962) B15(10.065,1.962) B16(9.465,1.962) B17(8.865,1.962) B18(8.265,1.962) B19(7.665,1.962) B20(7.065,1.962) B21(6.465,1.962) B22(5.865,1.962) B23(5.265,1.962) B24(4.665,1.962) B25(4.065,1.962) B26(3.465,1.962) B27(2.865,1.962) B28(2.265,1.962) B29(-1.745,1.962) B30(-2.345,1.962) B31(-2.945,1.962) B32(-3.545,1.962) B33(-4.145,1.962) B34(-4.745,1.962) B35(-5.345,1.962) B36(-5.945,1.962) B37(-6.545,1.962) B38(-7.145,1.962) B39(-7.745,1.962) B40(-8.345,1.962) B41(-8.945,1.962) B42(-9.545,1.962) B43(-14.455,1.962) B44(-15.055,1.962) B45(-15.655,1.962) B46(-16.255,1.962) B47(-16.855,1.962) B48(-17.455,1.962) B49(-18.055,1.962) B50(-18.655,1.962) B51(-19.255,1.962) B52(-19.855,1.962) B53(-20.455,1.962) B54(-21.055,1.962) B55(-21.655,1.962) B56(-22.255,1.962) B57(-22.855,1.962) B58(-23.455,1.962) B59(-24.055,1.962) B60(-24.655,1.962) B61(-25.255,1.962) B62(-25.855,1.962) B63(-26.455,1.962) B64(-27.055,1.962) B65(-27.655,1.962) B66(-28.255,1.962) B67(-28.855,1.962) B68(-29.455,1.962) B69(-30.055,1.962) B70(-30.655,1.962) OCP_A1(30.66,1.962) OCP_A2(30.06,1.962) OCP_A3(29.46,1.962) OCP_A4(28.86,1.962) OCP_A5(28.26,1.962) OCP_A6(27.66,1.962) OCP_A7(27.06,1.962) OCP_A8(26.46,1.962) OCP_A9(25.86,1.962) OCP_A10(25.26,1.962) OCP_A11(24.66,1.962) OCP_A12(24.06,1.962) OCP_A13(23.46,1.962) OCP_A14(22.86,1.962) OCP_B1(30.66,1.962) OCP_B2(30.06,1.962) OCP_B3(29.46,1.962) OCP_B4(28.86,1.962) OCP_B5(28.26,1.962) OCP_B6(27.66,1.962) OCP_B7(27.06,1.962) OCP_B8(26.46,1.962) OCP_B9(25.86,1.962) OCP_B10(25.26,1.962) OCP_B11(24.66,1.962) OCP_B12(24.06,1.962) OCP_B13(23.46,1.962) OCP_B14(22.86,1.962)
BERG1X2
  rect 1.575x1.575 hole 1.194: 1(0,0)
  round 1.575 hole 1.194: 2(0,-2.54)
C0201
  custom 0.075x0.075 smd: 1(-0.25,0) 2(0.25,0)
C0402
  rect 0.508x0.508 smd: 1(-0.432,0) 2(0.432,0)
C0603
  rect 0.762x0.762 smd: 1(-0.711,0) 2(0.711,0)
C1210_107H
  oval 1.143x3.048 smd: 1(-1.397,0) 2(1.397,0)
CON_AMP_EDGE_ME101681340131X
  rect 0.38x2.12 smd: A1(18.411,3.274) A4(16.611,3.274) A7(14.811,3.274) A10(13.011,3.274) A13(11.211,3.274) A16(9.411,3.274) A19(7.611,3.274) A22(5.811,3.274) A25(4.011,3.274) A28(2.211,3.274) A29(-1.799,3.274) A32(-3.599,3.274) A35(-5.399,3.274) A38(-7.199,3.274) A41(-8.999,3.274) A43(-14.509,3.274) A46(-16.309,3.274) A49(-18.109,3.274) A52(-19.909,3.274) A55(-21.709,3.274) A58(-23.509,3.274) A61(-25.309,3.274) A64(-27.109,3.274) A67(-28.909,3.274) A70(-30.709,3.274) B1(18.411,3.274) B4(16.611,3.274) B7(14.811,3.274) B10(13.011,3.274) B13(11.211,3.274) B16(9.411,3.274) B19(7.611,3.274) B22(5.811,3.274) B25(4.011,3.274) B28(2.211,3.274) B29(-1.799,3.274) B32(-3.599,3.274) B35(-5.399,3.274) B38(-7.199,3.274) B41(-8.999,3.274) B43(-14.509,3.274) B46(-16.309,3.274) B49(-18.109,3.274) B52(-19.909,3.274) B55(-21.709,3.274) B58(-23.509,3.274) B61(-25.309,3.274) B64(-27.109,3.274) B67(-28.909,3.274) B70(-30.709,3.274) OCP_A1(30.606,3.274) OCP_A4(28.806,3.274) OCP_A7(27.006,3.274) OCP_A10(25.206,3.274) OCP_A13(23.406,3.274) OCP_B1(30.606,3.274) OCP_B4(28.806,3.274) OCP_B7(27.006,3.274) OCP_B10(25.206,3.274) OCP_B13(23.406,3.274)
  rect 0.38x1.72 smd: A2(17.811,3.074) A3(17.211,3.074) A5(16.011,3.074) A6(15.411,3.074) A8(14.211,3.074) A9(13.611,3.074) A11(12.411,3.074) A12(11.811,3.074) A14(10.611,3.074) A15(10.011,3.074) A17(8.811,3.074) A18(8.211,3.074) A20(7.011,3.074) A21(6.411,3.074) A23(5.211,3.074) A24(4.611,3.074) A26(3.411,3.074) A27(2.811,3.074) A30(-2.399,3.074) A31(-2.999,3.074) A33(-4.199,3.074) A34(-4.799,3.074) A36(-5.999,3.074) A37(-6.599,3.074) A39(-7.799,3.074) A40(-8.399,3.074) A42(-9.599,3.074) A44(-15.109,3.074) A45(-15.709,3.074) A47(-16.909,3.074) A48(-17.509,3.074) A50(-18.709,3.074) A51(-19.309,3.074) A53(-20.509,3.074) A54(-21.109,3.074) A56(-22.309,3.074) A57(-22.909,3.074) A59(-24.109,3.074) A60(-24.709,3.074) A62(-25.909,3.074) A63(-26.509,3.074) A65(-27.709,3.074) A66(-28.309,3.074) A68(-29.509,3.074) A69(-30.109,3.074) B2(17.811,3.073) B3(17.211,3.073) B5(16.011,3.073) B6(15.411,3.073) B8(14.211,3.073) B9(13.611,3.073) B11(12.411,3.073) B12(11.811,3.073) B14(10.611,3.073) B15(10.011,3.073) B17(8.811,3.073) B18(8.211,3.073) B20(7.011,3.073) B21(6.411,3.073) B23(5.211,3.073) B24(4.611,3.073) B26(3.411,3.073) B27(2.811,3.073) B30(-2.399,3.073) B31(-2.999,3.073) B33(-4.199,3.073) B34(-4.799,3.073) B36(-5.999,3.073) B37(-6.599,3.073) B39(-7.799,3.073) B40(-8.399,3.073) B42(-9.599,3.073) B44(-15.109,3.073) B45(-15.709,3.073) B47(-16.909,3.073) B48(-17.509,3.073) B50(-18.709,3.073) B51(-19.309,3.073) B53(-20.509,3.073) B54(-21.109,3.073) B56(-22.309,3.073) B57(-22.909,3.073) B59(-24.109,3.073) B60(-24.709,3.073) B62(-25.909,3.073) B63(-26.509,3.073) B65(-27.709,3.073) B66(-28.309,3.073) B68(-29.509,3.073) B69(-30.109,3.073) OCP_A2(30.006,3.074) OCP_A3(29.406,3.074) OCP_A5(28.206,3.074) OCP_A6(27.606,3.074) OCP_A8(26.406,3.074) OCP_A9(25.806,3.074) OCP_A11(24.606,3.074) OCP_A12(24.006,3.074) OCP_A14(22.806,3.074) OCP_B2(30.006,3.073) OCP_B3(29.406,3.073) OCP_B5(28.206,3.073) OCP_B6(27.606,3.073) OCP_B8(26.406,3.073) OCP_B9(25.806,3.073) OCP_B11(24.606,3.073) OCP_B12(24.006,3.073) OCP_B14(22.806,3.073)
IMP_TP_1X3_35P
  round 0.635 hole 0.305: 1(0,0) 2(0.889,0) 3(1.778,0)
IMP_TP_1X4_35P
  round 0.635 hole 0.305: 1(0,0) 2(0.889,0) 3(1.778,0) 4(2.667,0)
LEDC1608X65N
  rect 0.8x0.95 smd: 1(-0.8,0) 2(0.8,0)
MH148_G8_288TB
  round 3.759 hole 3.759 unplated: (0,0)
  round 0.813 hole 0.457: 1(3.086,0)
QFN50P300X300X90-17
  oval 0.8x0.3 smd: 1(-1.45,0.75) 2(-1.45,0.25) 3(-1.45,-0.25) 4(-1.45,-0.75) 9(1.45,-0.75) 10(1.45,-0.25) 11(1.45,0.25) 12(1.45,0.75)
  oval 0.3x0.8 smd: 5(-0.75,-1.45) 6(-0.25,-1.45) 7(0.25,-1.45) 8(0.75,-1.45) 13(0.75,1.45) 14(0.25,1.45) 15(-0.25,1.45) 16(-0.75,1.45)
  rect 1.2x1.2 smd: 17(0,0)
R0201
  custom 0.075x0.075 smd: 1(-0.25,0) 2(0.25,0)
R0402
  rect 0.508x0.508 smd: 1(-0.432,0) 2(0.432,0)
SOIC127P600X175_8N
  oval 2x0.6 smd: 1(-2.45,1.905) 2(-2.45,0.635) 3(-2.45,-0.635) 4(-2.45,-1.905) 5(2.45,-1.905) 6(2.45,-0.635) 7(2.45,0.635) 8(2.45,1.905)
SOT65P210X110_5L
  oval 0.7x0.4 smd: 1(-0.9,0.65) 2(-0.9,0) 3(-0.9,-0.65) 4(0.9,-0.65) 5(0.9,0.65)
SOT65P210X110_5N
  oval 1.2x0.4 smd: 1(-0.95,0.65) 2(-0.95,0) 3(-0.95,-0.65) 4(0.95,-0.65) 5(0.95,0.65)
SOT95P237X117_3N
  oval 1.3x0.6 smd: 1(-1.05,0.95) 2(-1.05,-0.95) 3(1.05,0)
SW3PSMRA_2SH
  custom 0.813x0.813 smd: (-1.778,4.534) (1.778,4.534)
  rect 3.81x2.032 smd: 1(-3.683,-4.534) 3(3.683,-4.534)
  rect 1.016x2.286 smd: 2(0,-4.534)
TP3_PPROBEB
  round 0.254 hole 1.27 unplated: (-1.397,2.286) (-1.397,-2.286) (2.667,2.286) (2.667,-2.286)
  custom 0.267x0.267 hole 0.254: 1(0,0)
  rect 0.305x0.203 smd: 2(0.635,-0.225) 3(0.635,0.225)
TP_REC1P00X1P50
  rect 1x1.5 smd: TEST(0,0)
unnamed
  round 1.016 smd: (0,0)
unnamed#2
  round 1.067 hole 1.067 unplated: (-1.905,0) (1.905,0)
  round 0.711 hole 0.711 unplated: (-0.635,0) (0.635,0)
ZDI4PINS2R
  round 1.092 hole 0.711: 1(0,0) 2(2.54,0) 3(0,-2.54) 4(2.54,-2.54)
ZSE3PINS2R
  round 1.092 hole 0.711: 1(0,0) 2(2.54,0) 3(0,-2.54)

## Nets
AGND_2: P_CAL_CPU_OCP_0_N1.2 P_CAL_CPU_OCP_0_N1.3 P_CAL_CPU_OCP_0_N1.4 P_CAL_CPU_OCP_0_N1.5 P_CAL_CPU_OCP_0_N1.6 P_CAL_CPU_OCP_0_P1.2 P_CAL_CPU_OCP_0_P1.3 P_CAL_CPU_OCP_0_P1.4 P_CAL_CPU_OCP_0_P1.5 P_CAL_CPU_OCP_0_P1.6 P_CAL_OCP_CPU_B_0_N.2 P_CAL_OCP_CPU_B_0_N.3 P_CAL_OCP_CPU_B_0_N.4 P_CAL_OCP_CPU_B_0_N.5 P_CAL_OCP_CPU_B_0_N.6 P_CAL_OCP_CPU_B_0_P.2 P_CAL_OCP_CPU_B_0_P.3 P_CAL_OCP_CPU_B_0_P.4 P_CAL_OCP_CPU_B_0_P.5 P_CAL_OCP_CPU_B_0_P.6 P_OCPSTRDL.A1 P_OCPSTRDL.A2 P_OCPSTRDL.A3 P_OCPSTRDL.A4 P_OCPSTRDL.A5 P_OCPSTRDL.A6 P_OCPSTRDL.A13 P_OCPSTRDL.A16 P_OCPSTRDL.A19 P_OCPSTRDL.A22 P_OCPSTRDL.A25 P_OCPSTRDL.A28 P_OCPSTRDL.A29 P_OCPSTRDL.A32 P_OCPSTRDL.A35 P_OCPSTRDL.A38 P_OCPSTRDL.A41 P_OCPSTRDL.A43 P_OCPSTRDL.A46 P_OCPSTRDL.A49 P_OCPSTRDL.A52 P_OCPSTRDL.A55 P_OCPSTRDL.A58 P_OCPSTRDL.A61 P_OCPSTRDL.A64 P_OCPSTRDL.A67 P_OCPSTRDL.B13 P_OCPSTRDL.B16 P_OCPSTRDL.B19 P_OCPSTRDL.B22 P_OCPSTRDL.B25 P_OCPSTRDL.B28 P_OCPSTRDL.B29 P_OCPSTRDL.B32 P_OCPSTRDL.B35 P_OCPSTRDL.B38 P_OCPSTRDL.B41 P_OCPSTRDL.B43 P_OCPSTRDL.B46 P_OCPSTRDL.B49 P_OCPSTRDL.B52 P_OCPSTRDL.B55 P_OCPSTRDL.B58 P_OCPSTRDL.B61 P_OCPSTRDL.B64 P_OCPSTRDL.B67 P_OCPSTRDL.OCP_A6 P_OCPSTRDL.OCP_A10 P_OCPSTRDL.OCP_A13 P_OCPSTRDL.OCP_B10 P_OCPSTRDL.OCP_B13 P_SMA_BOT_2IN_DN_1.2 P_SMA_BOT_2IN_DN_1.3 P_SMA_BOT_2IN_DN_1.4 P_SMA_BOT_2IN_DN_1.5 P_SMA_BOT_2IN_DN_1.6 P_SMA_BOT_2IN_DN_2.2 P_SMA_BOT_2IN_DN_2.3 P_SMA_BOT_2IN_DN_2.4 P_SMA_BOT_2IN_DN_2.5 P_SMA_BOT_2IN_DN_2.6 P_SMA_BOT_2IN_DP_1.2 P_SMA_BOT_2IN_DP_1.3 P_SMA_BOT_2IN_DP_1.4 P_SMA_BOT_2IN_DP_1.5 P_SMA_BOT_2IN_DP_1.6 P_SMA_BOT_2IN_DP_2.2 P_SMA_BOT_2IN_DP_2.3 P_SMA_BOT_2IN_DP_2.4 P_SMA_BOT_2IN_DP_2.5 P_SMA_BOT_2IN_DP_2.6 P_SMA_BOT_5IN_DN_1.2 P_SMA_BOT_5IN_DN_1.3 P_SMA_BOT_5IN_DN_1.4 P_SMA_BOT_5IN_DN_1.5 P_SMA_BOT_5IN_DN_1.6 P_SMA_BOT_5IN_DN_2.2 P_SMA_BOT_5IN_DN_2.3 P_SMA_BOT_5IN_DN_2.4 P_SMA_BOT_5IN_DN_2.5 P_SMA_BOT_5IN_DN_2.6 P_SMA_BOT_5IN_DP_1.2 P_SMA_BOT_5IN_DP_1.3 P_SMA_BOT_5IN_DP_1.4 P_SMA_BOT_5IN_DP_1.5 P_SMA_BOT_5IN_DP_1.6 P_SMA_BOT_5IN_DP_2.2 P_SMA_BOT_5IN_DP_2.3 P_SMA_BOT_5IN_DP_2.4 P_SMA_BOT_5IN_DP_2.5 P_SMA_BOT_5IN_DP_2.6 P_SMA_BOT_10IN_DN_1.2 P_SMA_BOT_10IN_DN_1.3 P_SMA_BOT_10IN_DN_1.4 P_SMA_BOT_10IN_DN_1.5 P_SMA_BOT_10IN_DN_1.6 P_SMA_BOT_10IN_DN_2.2 P_SMA_BOT_10IN_DN_2.3 P_SMA_BOT_10IN_DN_2.4 P_SMA_BOT_10IN_DN_2.5 P_SMA_BOT_10IN_DN_2.6 P_SMA_BOT_10IN_DP_1.2 P_SMA_BOT_10IN_DP_1.3 P_SMA_BOT_10IN_DP_1.4 P_SMA_BOT_10IN_DP_1.5 P_SMA_BOT_10IN_DP_1.6 P_SMA_BOT_10IN_DP_2.2 P_SMA_BOT_10IN_DP_2.3 P_SMA_BOT_10IN_DP_2.4 P_SMA_BOT_10IN_DP_2.5 P_SMA_BOT_10IN_DP_2.6 P_SMA_TOP_2IN_DN_1.2 P_SMA_TOP_2IN_DN_1.3 P_SMA_TOP_2IN_DN_1.4 P_SMA_TOP_2IN_DN_1.5 P_SMA_TOP_2IN_DN_1.6 P_SMA_TOP_2IN_DN_2.2 P_SMA_TOP_2IN_DN_2.3 P_SMA_TOP_2IN_DN_2.4 P_SMA_TOP_2IN_DN_2.5 P_SMA_TOP_2IN_DN_2.6 P_SMA_TOP_2IN_DP_1.2 P_SMA_TOP_2IN_DP_1.3 P_SMA_TOP_2IN_DP_1.4 P_SMA_TOP_2IN_DP_1.5 P_SMA_TOP_2IN_DP_1.6 P_SMA_TOP_2IN_DP_2.2 P_SMA_TOP_2IN_DP_2.3 P_SMA_TOP_2IN_DP_2.4 P_SMA_TOP_2IN_DP_2.5 P_SMA_TOP_2IN_DP_2.6 P_SMA_TOP_5IN_DN_1.2 P_SMA_TOP_5IN_DN_1.3 P_SMA_TOP_5IN_DN_1.4 P_SMA_TOP_5IN_DN_1.5 P_SMA_TOP_5IN_DN_1.6 P_SMA_TOP_5IN_DN_2.2 P_SMA_TOP_5IN_DN_2.3 P_SMA_TOP_5IN_DN_2.4 P_SMA_TOP_5IN_DN_2.5 P_SMA_TOP_5IN_DN_2.6 P_SMA_TOP_5IN_DP_1.2 P_SMA_TOP_5IN_DP_1.3 P_SMA_TOP_5IN_DP_1.4 P_SMA_TOP_5IN_DP_1.5 P_SMA_TOP_5IN_DP_1.6 P_SMA_TOP_5IN_DP_2.2 P_SMA_TOP_5IN_DP_2.3 P_SMA_TOP_5IN_DP_2.4 P_SMA_TOP_5IN_DP_2.5 P_SMA_TOP_5IN_DP_2.6 P_SMA_TOP_10IN_DN_1.2 P_SMA_TOP_10IN_DN_1.3 P_SMA_TOP_10IN_DN_1.4 P_SMA_TOP_10IN_DN_1.5 P_SMA_TOP_10IN_DN_1.6 P_SMA_TOP_10IN_DN_2.2 P_SMA_TOP_10IN_DN_2.3 P_SMA_TOP_10IN_DN_2.4 P_SMA_TOP_10IN_DN_2.5 P_SMA_TOP_10IN_DN_2.6 P_SMA_TOP_10IN_DP_1.2 P_SMA_TOP_10IN_DP_1.3 P_SMA_TOP_10IN_DP_1.4 P_SMA_TOP_10IN_DP_1.5 P_SMA_TOP_10IN_DP_1.6 P_SMA_TOP_10IN_DP_2.2 P_SMA_TOP_10IN_DP_2.3 P_SMA_TOP_10IN_DP_2.4 P_SMA_TOP_10IN_DP_2.5 P_SMA_TOP_10IN_DP_2.6
